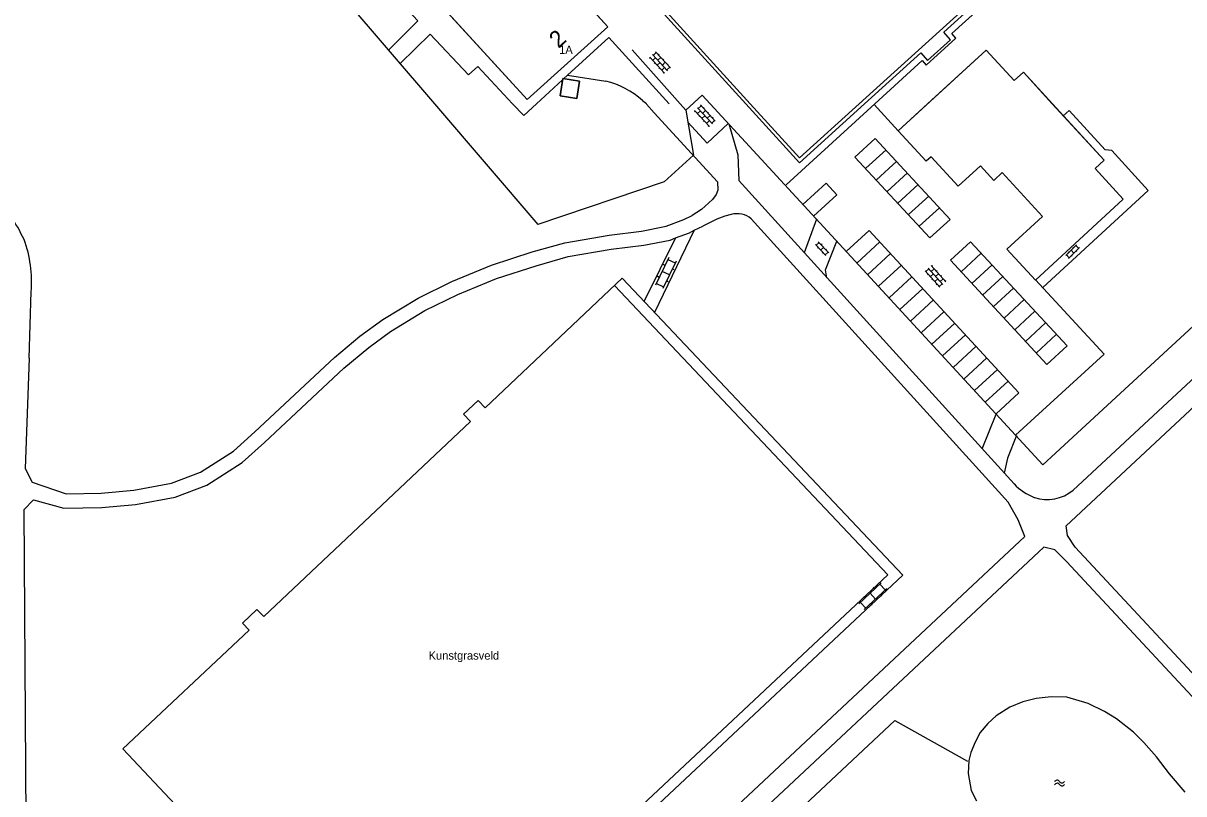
# Model space of a CAD drawing. Extents: x 148816 to 151297, y 399515 to 402500.
# Drawn here: x 149526 to 149700.3, y 400896.3 to 401012.1 of the extents above; entities that cross this region are included whole.
import ezdxf

# ---------------------------------------------------------------- set-up
doc = ezdxf.new("R2010")
doc.units = 0
for name, color, linetype in [('B01 Hoofdgebouw  [T] Norm', 7, 'Continuous'), ('B01 hoofgebouw', 7, 'Continuous'), ('S02 Open verharding  Norm', 7, 'Continuous'), ('S05 Water  Norm', 7, 'Continuous'), ('T03 Hek raster  [T] Norm', 7, 'Continuous'), ('T04 Haag heg  [D] Gem', 7, 'Continuous'), ('T09 Insteek water  [T] Norm', 7, 'Continuous'), ('V00 Kant verharding algemeen  [D] Norm', 7, 'Continuous'), ('V00 Kant verharding algemeen  [T] Norm', 7, 'Continuous'), ('V00 Kant verharding algemeen secundair  [T] Gem', 7, 'Continuous'), ('V00 Kant verharding algemeen secundair  [T] Norm', 7, 'Continuous'), ('Z02 huisnummer', 7, 'Continuous'), ('Z02 Huisnummer  [Tekst] Norm', 7, 'Continuous'), ('Z19 Overige Tekst  [Tekst] Gem', 7, 'Continuous')]:
    doc.layers.add(name, color=color, linetype=linetype)

msp = doc.modelspace()

# ---------------------------------------------------------------- linework, layer by layer
at = {"layer": 'B01 Hoofdgebouw  [T] Norm'}
for p, q in [((149613.8, 401011.58), (149605.26, 401020.99)), ((149584.79, 401019.16), (149601.71, 401000.62)), ((149601.71, 401000.62), (149613.8, 401011.58)), ((149606.66, 401001.21), (149607.04, 401003.77)), ((149607.04, 401003.77), (149609.56, 401003.39)), ((149609.56, 401003.39), (149609.17, 401000.81)), ((149609.17, 401000.81), (149606.66, 401001.21))]:
    msp.add_line(p, q, dxfattribs=at)
msp.add_lwpolyline([(149671.78, 400988.48), (149669.77, 400990.67), (149666.45, 400987.63), (149662.4, 400992.05), (149661.64, 400991.36), (149657.43, 400995.95), (149670.66, 401008.06), (149674.85, 401003.48), (149676.23, 401004.74), (149688.35, 400991.5), (149686.99, 400990.25), (149691.19, 400985.66), (149678.03, 400973.52), (149673.73, 400978.13), (149679.1, 400983.05), (149673.06, 400989.65)], close=True, dxfattribs=at)
at = {"layer": 'B01 hoofgebouw'}
for points in [[(149589.53, 401042.97), (149599.61, 401031.96), (149599.21, 401031.59), (149607.21, 401022.85), (149605.26, 401020.99), (149613.8, 401011.58), (149601.71, 401000.62), (149584.79, 401019.16), (149585.63, 401019.93), (149577.36, 401028.99), (149581.2, 401032.49), (149579.77, 401034.06), (149589.53, 401042.97)], [(149661.85, 401000), (149670.66, 401008.06), (149674.85, 401003.48), (149676.23, 401004.74), (149680.57, 401000)], [(149606.66, 401001.21), (149609.17, 401000.81), (149609.56, 401003.39), (149607.04, 401003.77), (149606.66, 401001.21)], [(149671.78, 400988.48), (149669.77, 400990.67), (149666.45, 400987.63), (149662.4, 400992.05), (149661.64, 400991.36), (149657.43, 400995.95), (149661.85, 401000)], [(149680.57, 401000), (149688.35, 400991.5), (149686.99, 400990.25), (149691.19, 400985.66), (149678.03, 400973.52), (149673.73, 400978.13), (149679.1, 400983.05), (149673.06, 400989.65), (149671.78, 400988.48)]]:
    msp.add_lwpolyline(points, dxfattribs=at)
at = {"layer": 'S02 Open verharding  Norm'}
for p, q in [((149620.21, 401006.88), (149620.1, 401006.78)), ((149620.11, 401006.99), (149622.35, 401004.57)), ((149620.55, 401007.4), (149622.79, 401004.97)), ((149620.99, 401006.92), (149620.55, 401006.52)), ((149621.1, 401007.7), (149620.66, 401007.29)), ((149620.89, 401006.15), (149620.78, 401006.05)), ((149621, 401007.81), (149623.23, 401005.38)), ((149621.67, 401006.19), (149621.23, 401005.78)), ((149621.77, 401006.96), (149621.33, 401006.55)), ((149621.44, 401007.33), (149621.55, 401007.43)), ((149622.45, 401006.23), (149622.01, 401005.82)), ((149622.11, 401006.59), (149622.22, 401006.7)), ((149621.57, 401005.41), (149621.46, 401005.31)), ((149621.91, 401005.05), (149622.35, 401005.45)), ((149622.25, 401004.68), (149622.14, 401004.58)), ((149623.13, 401005.49), (149622.69, 401005.08)), ((149622.79, 401005.86), (149622.9, 401005.96)), ((149627.28, 400999.41), (149629.52, 400996.98)), ((149627.83, 400999.71), (149627.38, 400999.3)), ((149627.72, 400999.82), (149629.96, 400997.39)), ((149628.16, 400999.34), (149628.27, 400999.44)), ((149626.94, 400998.89), (149626.83, 400998.79)), ((149626.84, 400999), (149629.08, 400996.58)), ((149627.72, 400998.93), (149627.28, 400998.53)), ((149627.62, 400998.16), (149627.51, 400998.06)), ((149628.4, 400998.2), (149627.96, 400997.79)), ((149628.5, 400998.97), (149628.06, 400998.56)), ((149628.3, 400997.42), (149628.19, 400997.32)), ((149628.64, 400997.05), (149629.08, 400997.46)), ((149629.18, 400998.24), (149628.74, 400997.83)), ((149628.84, 400998.6), (149628.95, 400998.7)), ((149629.86, 400997.5), (149629.42, 400997.09)), ((149629.52, 400997.87), (149629.63, 400997.97)), ((149628.98, 400996.69), (149628.87, 400996.59)), ((149645, 400978.86), (149646.56, 400977.18)), ((149645.1, 400978.75), (149645.54, 400979.16)), ((149645.44, 400978.38), (149645.33, 400978.28)), ((149645.43, 400979.27), (149647, 400977.58)), ((149646.22, 400978.43), (149645.78, 400978.02)), ((149645.99, 400978.89), (149645.88, 400978.79)), ((149684.22, 400978.81), (149682.58, 400977.19)), ((149684.64, 400978.38), (149683, 400976.76)), ((149683.75, 400978.35), (149683.65, 400978.46)), ((149684.11, 400978.7), (149684.53, 400978.28)), ((149622.97, 400976.89), (149620.97, 400972.75)), ((149622.84, 400976.62), (149623.92, 400976.1)), ((149646.12, 400977.65), (149646.01, 400977.55)), ((149646.46, 400977.29), (149646.9, 400977.69)), ((149646.67, 400978.16), (149646.56, 400978.06)), ((149682.69, 400977.3), (149683.11, 400976.87)), ((149683.04, 400977.65), (149682.94, 400977.75)), ((149683.82, 400977.57), (149683.4, 400978)), ((149683.57, 400977.11), (149683.47, 400977.22)), ((149684.28, 400977.82), (149684.18, 400977.92)), ((149623.06, 400974.3), (149621.97, 400974.82)), ((149624.06, 400976.37), (149622.06, 400972.23)), ((149622.41, 400975.72), (149622.14, 400975.85)), ((149623.76, 400975.07), (149623.49, 400975.2)), ((149663.7, 400972.44), (149661.49, 400974.9)), ((149661.59, 400974.78), (149662.04, 400975.19)), ((149664.14, 400972.84), (149661.94, 400975.3)), ((149662.82, 400975.21), (149662.37, 400974.81)), ((149664.59, 400973.24), (149662.39, 400975.7)), ((149662.49, 400975.59), (149662.6, 400975.69)), ((149663.15, 400974.84), (149663.27, 400974.94)), ((149621.11, 400973.02), (149622.19, 400972.5)), ((149621.54, 400973.92), (149621.27, 400974.05)), ((149622.89, 400973.27), (149622.62, 400973.4)), ((149661.93, 400974.41), (149661.82, 400974.31)), ((149662.26, 400974.04), (149662.71, 400974.44)), ((149662.6, 400973.67), (149662.48, 400973.57)), ((149662.93, 400973.3), (149663.38, 400973.7)), ((149663.04, 400974.07), (149663.49, 400974.47)), ((149663.71, 400973.32), (149664.16, 400973.72)), ((149663.82, 400974.1), (149663.93, 400974.2)), ((149664.49, 400973.35), (149664.6, 400973.45)), ((149663.26, 400972.92), (149663.15, 400972.82)), ((149663.6, 400972.55), (149664.04, 400972.95)), ((149654.88, 400928.04), (149651.52, 400924.89)), ((149654.66, 400927.83), (149655.48, 400926.96)), ((149652.47, 400925.78), (149652.26, 400926)), ((149655.7, 400927.16), (149652.34, 400924.02)), ((149654.02, 400925.59), (149653.2, 400926.46)), ((149653.93, 400927.15), (149653.72, 400927.37)), ((149654.96, 400926.05), (149654.75, 400926.27)), ((149651.74, 400925.1), (149652.56, 400924.22)), ((149653.5, 400924.69), (149653.29, 400924.9))]:
    msp.add_line(p, q, dxfattribs=at)
at = {"layer": 'S05 Water  Norm'}
for centre, start, end in [((149681.29, 400897.95), 30.5989, 154.4539), ((149682.02, 400898.39), 210.5989, 334.4539), ((149681.31, 400897.5), 30.5989, 154.4539), ((149682.04, 400897.94), 210.5989, 334.4539)]:
    msp.add_arc(centre, 0.425, start, end, dxfattribs=at)
at = {"layer": 'T03 Hek raster  [T] Norm'}
for p, q in [((149574.17, 401015.89), (149587.77, 401000)), ((149625.53, 400999.04), (149627.97, 401001.31)), ((149587.77, 401000), (149603.29, 400981.87))]:
    msp.add_line(p, q, dxfattribs=at)
for points in [[(149628.98, 401058.57), (149624.59, 401054.56), (149623.56, 401055.7), (149620.06, 401052.58), (149621.08, 401051.44), (149602.82, 401034.89), (149634.52, 401000)], [(149652.38, 401000), (149660.81, 401007.65), (149661.83, 401006.5), (149665.29, 401009.62), (149664.29, 401010.77), (149694.61, 401038.26), (149695.63, 401037.14), (149699.08, 401040.26), (149698.06, 401041.36), (149716.29, 401057.94)], [(149617.48, 401008.09), (149624.68, 401000)], [(149629.18, 401000), (149627.97, 401001.31)], [(149624.68, 401000), (149625.53, 400999.04), (149626.69, 400992.29)], [(149737.93, 401000), (149679.14, 400945.78), (149629.18, 401000)], [(149634.52, 401000), (149642.6, 400991.11), (149652.38, 401000)], [(149626.69, 400992.29), (149622.26, 400988.26), (149603.29, 400981.87)]]:
    msp.add_lwpolyline(points, dxfattribs=at)
at = {"layer": 'T04 Haag heg  [D] Gem'}
for q in [(149626.91, 400879.22), (149667.82, 400901.24)]:
    msp.add_line((149656.92, 400907.37), q, dxfattribs=at)
msp.add_lwpolyline([(149583.15, 400858.89), (149658.11, 400929.18), (149615.99, 400973.79), (149595.38, 400954.33), (149594.35, 400955.42), (149592.16, 400953.36), (149593.19, 400952.27), (149562.14, 400922.95), (149561.11, 400924.04), (149558.93, 400921.99), (149559.96, 400920.9), (149540.98, 400903.08), (149581.77, 400859.69)], dxfattribs=at)
at = {"layer": 'T09 Insteek water  [T] Norm'}
msp.add_lwpolyline([(149700.52, 400896.57), (149698.17, 400899.34), (149696.2, 400901.91), (149694.31, 400904.03), (149692.75, 400905.57), (149690.22, 400907.58), (149688.39, 400908.71), (149685.94, 400909.91), (149682.73, 400910.83), (149680.42, 400910.91), (149678.14, 400910.67), (149676.13, 400910.15), (149674.18, 400909.35), (149672.16, 400908.07), (149670.87, 400906.92), (149669.76, 400905.56), (149669.01, 400904.09), (149668.35, 400902.56), (149668.03, 400901.32), (149667.94, 400899.36), (149668.41, 400896.85), (149669.18, 400895.29)], dxfattribs=at)
at = {"layer": 'V00 Kant verharding algemeen  [D] Norm'}
msp.add_lwpolyline([(149631.91, 400997.04), (149628.72, 400994.1), (149625.84, 400997.23)], dxfattribs=at)
at = {"layer": 'V00 Kant verharding algemeen  [T] Norm'}
for p, q in [((149603.54, 401034.85), (149635.21, 401000)), ((149613.99, 401009.96), (149607.76, 401004.28)), ((149623.02, 401000), (149613.99, 401009.96)), ((149607.01, 401003.59), (149603.11, 401000)), ((149607.76, 401004.28), (149607.18, 401003.75)), ((149607.76, 401004.28), (149613.5, 401003.37)), ((149599.52, 401000), (149601.18, 400998.22)), ((149603.11, 401000), (149601.18, 400998.22)), ((149619.01, 401000.49), (149619.62, 401000.06)), ((149619.62, 400999.94), (149620.79, 400998.65)), ((149635.21, 401000), (149642.6, 400991.86)), ((149657.43, 400995.95), (149653.82, 400999.9)), ((149746.03, 401000), (149683.7, 400941.95)), ((149620.79, 400998.65), (149630.3, 400988.27)), ((149682.64, 400936.59), (149740.19, 400990.27)), ((149630.36, 400987.01), (149630.07, 400986.37)), ((149630.3, 400988.27), (149630.36, 400987.01)), ((149674.82, 400942.89), (149633.5, 400988.45)), ((149629.54, 400985.64), (149627.89, 400984.13)), ((149630.07, 400986.37), (149629.54, 400985.64)), ((149627.89, 400984.13), (149626.48, 400983.23)), ((149630.21, 400982.65), (149628.09, 400981.63)), ((149631.39, 400983.11), (149630.21, 400982.65)), ((149632.36, 400983.37), (149631.39, 400983.11)), ((149673.95, 400940.13), (149635.37, 400982.72)), ((149645.15, 400982.67), (149643.33, 400977.61)), ((149526.91, 400961.78), (149527.21, 400971.77)), ((149526.91, 400961.78), (149526.3, 400945.2)), ((149526.3, 400945.2), (149527.35, 400943.15)), ((149527.56, 400940.52), (149526.1, 400939)), ((149675.45, 400937.5), (149673.95, 400940.13)), ((149526.1, 400939), (149526.81, 400832.69)), ((149676.46, 400934.97), (149675.45, 400937.5)), ((149682.84, 400935.12), (149682.64, 400936.59)), ((149603.73, 400866.94), (149676.46, 400934.97)), ((149684.02, 400933.41), (149682.84, 400935.12)), ((149679.28, 400933.38), (149609.28, 400867.84)), ((149680.94, 400933), (149679.28, 400933.38)), ((149682.71, 400931.25), (149680.94, 400933)), ((149705.84, 400909.91), (149684.02, 400933.41)), ((149705.92, 400906.24), (149682.71, 400931.25))]:
    msp.add_line(p, q, dxfattribs=at)
for points in [[(149715.58, 401057.98), (149651.58, 401000)], [(149653.93, 401000), (149661.02, 401006.48), (149661.61, 401005.81), (149666.09, 401009.85), (149665.49, 401010.53), (149694.75, 401037.05), (149695.36, 401036.35), (149699.83, 401040.42), (149699.22, 401041.09), (149716.72, 401056.93)], [(149574.51, 401024.04), (149585.3, 401012.47), (149580.96, 401008.15)], [(149582.65, 401006.03), (149587.13, 401010.47), (149592.9, 401004.33), (149594.29, 401005.62), (149599.52, 401000)], [(149640.62, 400987.84), (149653.93, 401000)], [(149651.58, 401000), (149642.6, 400991.86)], [(149679.14, 400972.4), (149694.97, 400986.96), (149689.49, 400992.97), (149688.5, 400993.09), (149683.09, 400999.01), (149682.21, 400998.21)], [(149631.97, 400996.96), (149633.33, 400992.35), (149633.51, 400988.46)], [(149527.35, 400943.15), (149532.45, 400941.38), (149537.71, 400941.49), (149542.61, 400941.93), (149548.27, 400942.98), (149552.63, 400944.64), (149557.59, 400947.82), (149560.82, 400950.71), (149572.75, 400961.87), (149576.59, 400965.07), (149580.01, 400967.58), (149585.32, 400970.81), (149590.39, 400973.31), (149596.37, 400975.76), (149602.43, 400977.73), (149607.37, 400979.13), (149614.02, 400980.27), (149618.89, 400980.86), (149622.6, 400981.6), (149625.21, 400982.6), (149626.48, 400983.23)], [(149626.81, 400981), (149620.85, 400968.65)], [(149626.81, 400981), (149628.09, 400981.63)], [(149527.56, 400940.52), (149532.11, 400939.23), (149537.83, 400939.35), (149542.9, 400939.8), (149548.85, 400940.91), (149553.6, 400942.71), (149558.89, 400946.1), (149562.27, 400949.12), (149574.17, 400960.26), (149577.91, 400963.38), (149581.2, 400965.79), (149586.35, 400968.93), (149591.27, 400971.35), (149597.11, 400973.74), (149603.05, 400975.67), (149607.85, 400977.04), (149614.33, 400978.14), (149619.23, 400978.74), (149623.2, 400979.53), (149624, 400979.84)], [(149624, 400979.84), (149619.27, 400970.32)], [(149646.73, 400973.85), (149646.5, 400975.03), (149648.2, 400979.36)], [(149675.06, 400950.23), (149688.37, 400962.39), (149678.07, 400973.56)], [(149582.06, 400860.05), (149655.85, 400929.25), (149614.83, 400972.69)], [(149670.02, 400948.18), (149672.14, 400953.38)], [(149675.19, 400950.18), (149673.82, 400946.75), (149673.34, 400944.52)]]:
    msp.add_lwpolyline(points, dxfattribs=at)
for centre, radius, start, end in [((149610.78, 400991.46), 12.22, 47.6684, 77.1407), ((149484.85, 400958.58), 46.36, 26.9811, 37.2061), ((149633.2, 400979.98), 3.5, 51.6821, 103.9464), ((149508.63, 400973.29), 18.64, 355.3092, 19.8035), ((149681.16, 400949.11), 8.88, 224.4552, 248.2514), ((149679.82, 400946.59), 6.05, 251.2334, 309.9465)]:
    msp.add_arc(centre, radius, start, end, dxfattribs=at)
at = {"layer": 'V00 Kant verharding algemeen secundair  [T] Gem'}
for p, q in [((149652.58, 400990.33), (149655.61, 400993.1)), ((149654.18, 400988.58), (149657.21, 400991.35)), ((149655.78, 400986.84), (149658.81, 400989.6)), ((149657.39, 400985.09), (149660.41, 400987.86)), ((149658.99, 400983.34), (149662.01, 400986.11)), ((149660.59, 400981.59), (149663.61, 400984.36)), ((149654.68, 400979.24), (149651.24, 400976.07)), ((149656.29, 400977.5), (149652.84, 400974.32)), ((149669.91, 400977.53), (149666.88, 400974.74)), ((149657.9, 400975.76), (149654.45, 400972.58)), ((149671.52, 400975.79), (149668.49, 400972.99)), ((149659.5, 400974.01), (149656.06, 400970.84)), ((149673.13, 400974.05), (149670.1, 400971.25)), ((149661.11, 400972.27), (149657.66, 400969.09)), ((149674.73, 400972.31), (149671.71, 400969.51)), ((149662.71, 400970.53), (149659.27, 400967.35)), ((149676.34, 400970.57), (149673.32, 400967.77)), ((149664.32, 400968.78), (149660.87, 400965.61)), ((149677.95, 400968.83), (149674.93, 400966.03)), ((149665.93, 400967.04), (149662.48, 400963.87)), ((149679.56, 400967.09), (149676.54, 400964.29)), ((149667.53, 400965.3), (149664.09, 400962.12)), ((149681.17, 400965.35), (149678.14, 400962.55)), ((149669.14, 400963.56), (149665.69, 400960.38)), ((149670.74, 400961.81), (149667.3, 400958.64)), ((149672.35, 400960.07), (149668.91, 400956.9)), ((149673.96, 400958.33), (149670.51, 400955.15))]:
    msp.add_line(p, q, dxfattribs=at)
msp.add_lwpolyline([(149624, 400979.84), (149626.07, 400980.63), (149626.81, 400981)], dxfattribs=at)
at = {"layer": 'V00 Kant verharding algemeen secundair  [T] Norm'}
msp.add_line((149653.08, 400980.98), (149649.63, 400977.81), dxfattribs=at)
msp.add_lwpolyline([(149650.93, 400992), (149662.19, 400979.84), (149665.21, 400982.61), (149653.95, 400994.8)], close=True, dxfattribs=at)
for points in [[(149643.12, 400984.88), (149646.59, 400988.06), (149648.2, 400986.32), (149644.72, 400983.13)], [(149672.12, 400953.41), (149675.56, 400956.59), (149653.08, 400980.98)], [(149668.3, 400979.27), (149682.78, 400963.61), (149679.75, 400960.81), (149665.28, 400976.48), (149668.3, 400979.27)]]:
    msp.add_lwpolyline(points, dxfattribs=at)

# ---------------------------------------------------------------- texts
at = {"layer": 'Z02 huisnummer'}
msp.add_text('2', height=2.5, rotation=42.2043, dxfattribs=at).set_placement((149606.4, 401008.24))
at = {"layer": 'Z02 Huisnummer  [Tekst] Norm'}
msp.add_text('1A', height=1.25, dxfattribs=at).set_placement((149606.5, 401007.49))
at = {"layer": 'Z19 Overige Tekst  [Tekst] Gem'}
msp.add_text('Kunstgrasveld', height=1.25, dxfattribs=at).set_placement((149586.9, 400916.49))

doc.saveas('drawing.dxf')
